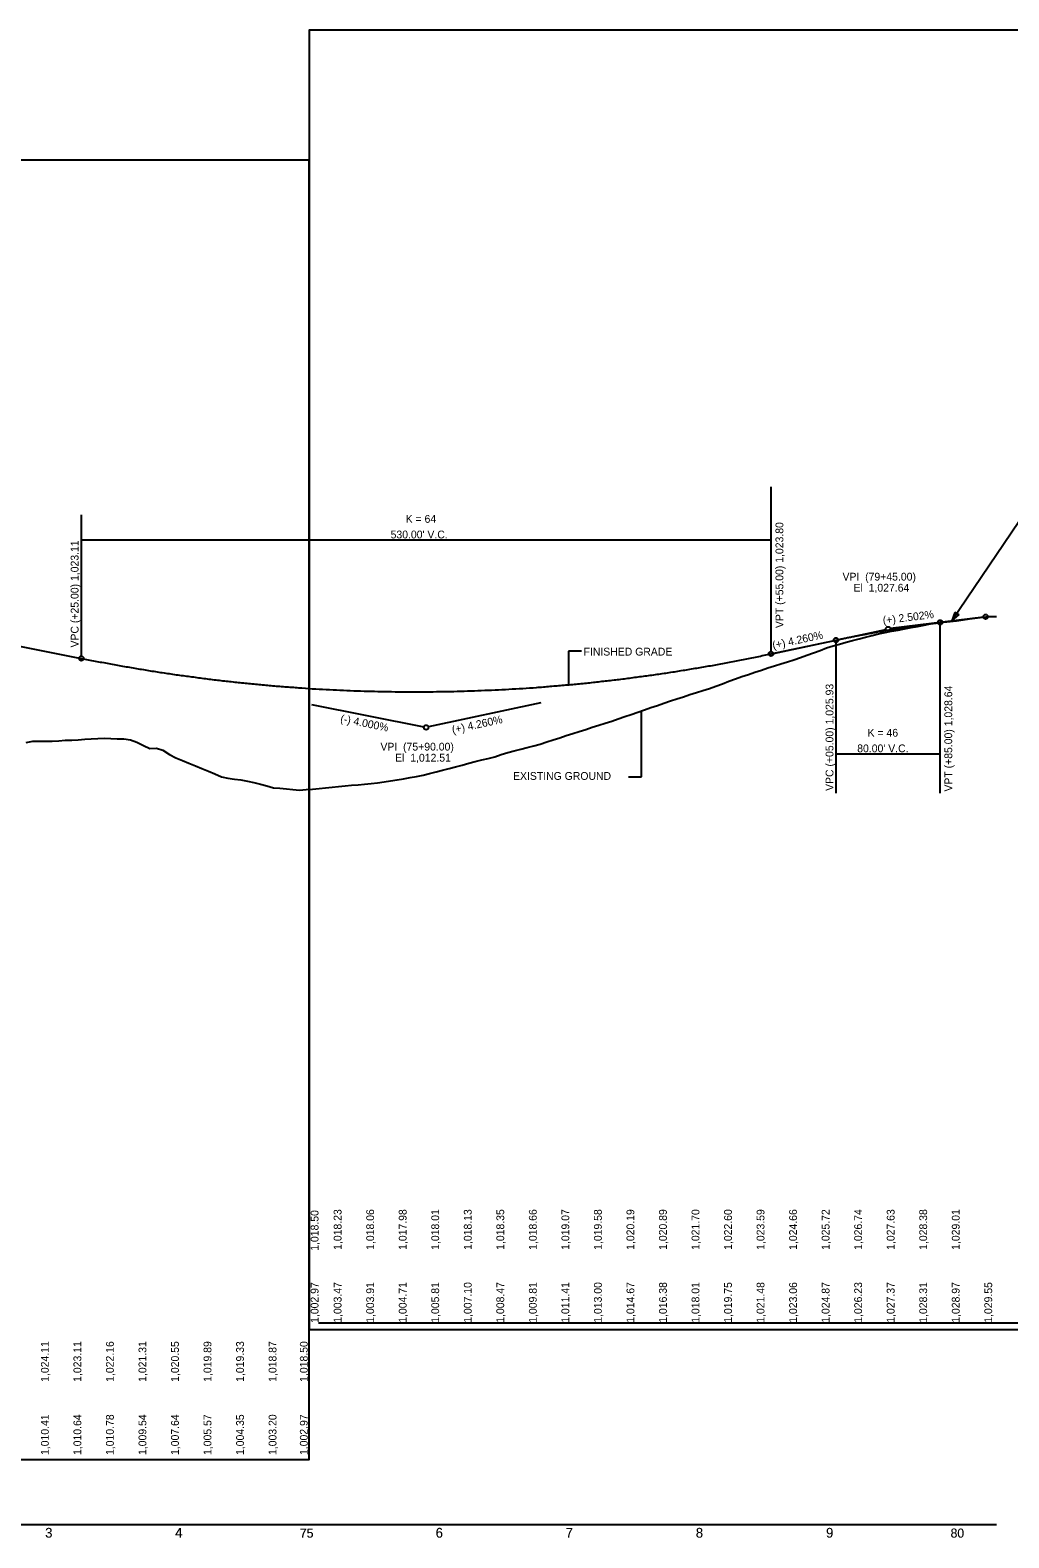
# Model space of a CAD drawing. Extents: x 889661 to 1611291, y 880491 to 1094402.
# Drawn here: x 892763 to 893515, y 880491 to 881649 of the extents above; entities that cross this region are included whole.
import ezdxf

# ---------------------------------------------------------------- set-up
doc = ezdxf.new("R2010")
doc.units = 0
for name, color, linetype in [('Default', 7, 'Continuous'), ('RD_DDB_Datum', 7, 'Continuous'), ('RD_DDB_EX_Tx', 7, 'Continuous'), ('RD_DDB_GradeTX', 7, 'Continuous'), ('RD_DDB_PI', 7, 'Continuous'), ('RD_DDB_PR_Tx', 7, 'Continuous'), ('RD_DDB_Profile_EX', 7, 'Continuous'), ('RD_DDB_Profile_PR', 7, 'Continuous'), ('RD_DDB_StaTX', 7, 'Continuous'), ('RD_DDB_StripGrade_EX', 7, 'Continuous'), ('RD_DDB_StripGrade_PR', 7, 'Continuous'), ('RD_DDB_VCLbl', 7, 'Continuous'), ('RD_GPK_Profile_Cell', 7, 'Continuous'), ('RD_TX_Profile', 7, 'Continuous')]:
    doc.layers.add(name, color=color, linetype=linetype)

msp = doc.modelspace()

# ---------------------------------------------------------------- linework, layer by layer
at = {"layer": 'Default'}
for points in [[(892976.9, 880651.1), (894476.9, 880651.1), (894476.9, 881649.3), (892976.9, 881649.3)], [(891476.9, 880551.1), (892976.9, 880551.1), (892976.9, 881549.3), (891476.9, 881549.3)]]:
    msp.add_lwpolyline(points, close=True, dxfattribs=at)
at = {"layer": 'RD_DDB_Datum'}
msp.add_line((892984.2, 880656.1), (895508.1, 880656.1), dxfattribs=at)
at = {"layer": 'RD_DDB_EX_Tx'}
for p, q in [((893232.3, 881075.7), (893232.3, 881126.2)), ((893222.5, 881075.7), (893232.3, 881075.7))]:
    msp.add_line(p, q, dxfattribs=at)
at = {"layer": 'RD_DDB_PI'}
for p, q in [((893495.2, 881198.4), (893423.7, 881189.5)), ((893333.9, 881170.5), (893420.2, 881188.9)), ((892978.7, 881131.3), (893065.2, 881114)), ((893155, 881132.4), (893068.7, 881114))]:
    msp.add_line(p, q, dxfattribs=at)
for centre in [(893496.9, 881198.6), (893421.9, 881189.2), (893066.9, 881113.6)]:
    msp.add_circle(centre, 1.75, dxfattribs=at)
at = {"layer": 'RD_DDB_PR_Tx'}
for p, q in [((893176.4, 881172.1), (893176.4, 881146.4)), ((893186.4, 881172.1), (893176.4, 881172.1))]:
    msp.add_line(p, q, dxfattribs=at)
at = {"layer": 'RD_DDB_Profile_EX'}
for points in [[(893419.6, 881186.5), (893424.6, 881187.5), (893429.6, 881188.4), (893434.6, 881189.4), (893439.6, 881190.3), (893444.6, 881191.1), (893449.6, 881192.1), (893454.6, 881193.1), (893459.6, 881193.9), (893464.6, 881194.4), (893469.6, 881194.9), (893474.6, 881195.6), (893479.6, 881196.3), (893484.6, 881197), (893489.6, 881197.7), (893494.6, 881198.4), (893499.6, 881198.8), (893504.6, 881198.8), (893505.3, 881198.8)], [(892919.6, 881073.8), (892924.6, 881073.2), (892929.6, 881072.4), (892934.6, 881071.2), (892939.6, 881070), (892944.6, 881068.6), (892949.6, 881067.3), (892954.6, 881066.8), (892959.6, 881066.3), (892964.6, 881066), (892969.6, 881065.4), (892974.6, 881065.8), (892979.6, 881066.1), (892984.6, 881066.7), (892989.6, 881067.3), (892994.6, 881067.8), (892999.6, 881068.2), (893004.6, 881068.7), (893009.6, 881069.1), (893014.6, 881069.5), (893019.6, 881070), (893024.6, 881070.4), (893029.6, 881070.9), (893034.6, 881071.7), (893039.6, 881072.5), (893044.6, 881073.4), (893049.6, 881074.2), (893054.6, 881075.1), (893059.6, 881075.9), (893064.6, 881076.9), (893069.6, 881078.2), (893074.6, 881079.5), (893079.6, 881080.8), (893084.6, 881082.1), (893089.6, 881083.4), (893094.6, 881084.7), (893099.6, 881086), (893104.6, 881087.3), (893109.6, 881088.6), (893114.6, 881089.8), (893119.6, 881091.1), (893124.6, 881092.7), (893129.6, 881094.2), (893134.6, 881095.5), (893139.6, 881096.9), (893144.6, 881098.2), (893149.6, 881099.5), (893154.6, 881100.8), (893159.6, 881102.5), (893164.6, 881104.1), (893169.6, 881105.7), (893174.6, 881107.4), (893179.6, 881109), (893184.6, 881110.5), (893189.6, 881112.1), (893194.6, 881113.7), (893199.6, 881115.3), (893204.6, 881116.9), (893209.6, 881118.5), (893214.6, 881120.2), (893219.6, 881121.9), (893224.6, 881123.6), (893229.6, 881125.3), (893234.6, 881127.1), (893239.6, 881128.8), (893244.6, 881130.5), (893249.6, 881132.2), (893254.6, 881133.9), (893259.6, 881135.5), (893264.6, 881137.2), (893269.6, 881138.8), (893274.6, 881140.4), (893279.6, 881142), (893284.6, 881143.6), (893289.6, 881145.4), (893294.6, 881147.2), (893299.6, 881149), (893304.6, 881150.8), (893309.6, 881152.6), (893314.6, 881154.3), (893319.6, 881156.1), (893324.6, 881157.7), (893329.6, 881159.3), (893334.6, 881160.9), (893339.6, 881162.5), (893344.6, 881164.1), (893349.6, 881165.6), (893354.6, 881167.2), (893359.6, 881169.1), (893364.6, 881170.9), (893369.6, 881172.8), (893374.6, 881174.7), (893379.6, 881176.3), (893384.6, 881177.6), (893389.6, 881179), (893394.6, 881180.3), (893399.6, 881181.6), (893404.6, 881182.9), (893409.6, 881184.3), (893414.6, 881185.4), (893419.6, 881186.5)], [(892759.6, 881102), (892764.6, 881103), (892769.6, 881103), (892774.6, 881103.1), (892779.6, 881103.1), (892784.6, 881103.3), (892789.6, 881103.7), (892794.6, 881103.9), (892799.6, 881104.1), (892804.6, 881104.5), (892809.6, 881104.9), (892814.6, 881105.2), (892819.6, 881105.3), (892824.6, 881105.1), (892829.6, 881104.8), (892834.6, 881104.8), (892839.6, 881104), (892844.6, 881102.2), (892849.6, 881099.8), (892854.6, 881097.5), (892859.6, 881097.6), (892864.6, 881096.2), (892869.6, 881092.8), (892874.6, 881090.2), (892879.6, 881088.1), (892884.6, 881086.1), (892889.6, 881084), (892894.6, 881081.9), (892899.6, 881079.9), (892904.6, 881077.8), (892909.6, 881075.7), (892914.6, 881074.7), (892919.6, 881073.8)]]:
    msp.add_lwpolyline(points, dxfattribs=at)
at = {"layer": 'RD_DDB_Profile_PR'}
for p, q in [((893461.9, 881194.3), (893496.9, 881198.6)), ((892666.9, 881193.6), (892801.9, 881166.6)), ((893331.9, 881170.1), (893381.9, 881180.7))]:
    msp.add_line(p, q, dxfattribs=at)
for points in [[(893381.9, 881180.7), (893383.5, 881181.1), (893385.1, 881181.4), (893386.7, 881181.7), (893388.3, 881182.1), (893389.9, 881182.4), (893391.5, 881182.7), (893393.1, 881183), (893394.7, 881183.4), (893396.3, 881183.7), (893397.9, 881184), (893399.5, 881184.3), (893401.1, 881184.6), (893402.7, 881184.9), (893404.3, 881185.2), (893405.9, 881185.5), (893407.5, 881185.8), (893409.1, 881186.1), (893410.7, 881186.4), (893412.3, 881186.7), (893413.9, 881187), (893415.5, 881187.3), (893417.1, 881187.5), (893418.7, 881187.8), (893420.3, 881188.1), (893421.9, 881188.4), (893423.5, 881188.6), (893425.1, 881188.9), (893426.7, 881189.2), (893428.3, 881189.4), (893429.9, 881189.7), (893431.5, 881189.9), (893433.1, 881190.2), (893434.7, 881190.4), (893436.3, 881190.7), (893437.9, 881190.9), (893439.5, 881191.2), (893441.1, 881191.4), (893442.7, 881191.6), (893444.3, 881191.9), (893445.9, 881192.1), (893447.5, 881192.3), (893449.1, 881192.6), (893450.7, 881192.8), (893452.3, 881193), (893453.9, 881193.2), (893455.5, 881193.4), (893457.1, 881193.6), (893458.7, 881193.8), (893460.3, 881194.1), (893461.9, 881194.3)], [(892801.9, 881166.6), (892812.5, 881164.6), (892823.1, 881162.6), (892833.7, 881160.7), (892844.3, 881158.9), (892854.9, 881157.1), (892865.5, 881155.5), (892876.1, 881153.9), (892886.7, 881152.5), (892897.3, 881151.1), (892907.9, 881149.8), (892918.5, 881148.6), (892929.1, 881147.5), (892939.7, 881146.5), (892950.3, 881145.5), (892960.9, 881144.7), (892971.5, 881143.9), (892982.1, 881143.2), (892992.7, 881142.7), (893003.3, 881142.2), (893013.9, 881141.7), (893024.5, 881141.4), (893035.1, 881141.2), (893045.7, 881141), (893056.3, 881141), (893066.9, 881141), (893077.5, 881141.1), (893088.1, 881141.3), (893098.7, 881141.6), (893109.3, 881142), (893119.9, 881142.4), (893130.5, 881143), (893141.1, 881143.6), (893151.7, 881144.3), (893162.3, 881145.2), (893172.9, 881146.1), (893183.5, 881147), (893194.1, 881148.1), (893204.7, 881149.3), (893215.3, 881150.5), (893225.9, 881151.9), (893236.5, 881153.3), (893247.1, 881154.8), (893257.7, 881156.4), (893268.3, 881158.1), (893278.9, 881159.9), (893289.5, 881161.7), (893300.1, 881163.7), (893310.7, 881165.7), (893321.3, 881167.9), (893331.9, 881170.1)]]:
    msp.add_spline(points, degree=3, dxfattribs=at)
at = {"layer": 'RD_DDB_VCLbl'}
for p, q in [((893331.9, 881298.4), (893331.9, 881171.8)), ((892801.9, 881276.9), (892801.9, 881168.4)), ((892801.9, 881257.6), (893331.9, 881257.6)), ((893461.9, 881063.2), (893461.9, 881192.5)), ((893381.9, 881063.2), (893381.9, 881179)), ((893381.9, 881093.2), (893461.9, 881093.2))]:
    msp.add_line(p, q, dxfattribs=at)
for centre in [(893461.9, 881194.3), (893381.9, 881180.7), (892801.9, 881166.6), (893331.9, 881170.1)]:
    msp.add_circle(centre, 1.75, dxfattribs=at)
at = {"layer": 'RD_GPK_Profile_Cell'}
msp.add_line((890419.6, 880501.1), (893505.3, 880501.1), dxfattribs=at)
at = {"layer": 'RD_TX_Profile'}
msp.add_lwpolyline([(893524.2, 881271.5), (893522.4, 881271.5), (893470.9, 881195.4)], dxfattribs=at)
msp.add_lwpolyline([(893473.2, 881202), (893470.9, 881195.4), (893476.2, 881200)], close=True, dxfattribs=at)

# ---------------------------------------------------------------- texts
at = {"layer": 'RD_DDB_EX_Tx'}
msp.add_text('EXISTING GROUND', height=6, dxfattribs=at).set_placement((893133.7, 881073.3))
at = {"layer": 'RD_DDB_GradeTX'}
for s, rotation, p in [('(+) 2.502%', 7.1304, (893418.2, 881192.8)), ('(+) 4.260%', 12.0243, (893333.7, 881173.7)), ('(-) 4.000%', 348.6902, (893000.6, 881117.7)), ('(+) 4.260%', 12.0243, (893087.4, 881108.8))]:
    msp.add_text(s, height=6, rotation=rotation, dxfattribs=at).set_placement(p)
at = {"layer": 'RD_DDB_PI'}
for s, p in [('VPI  (79+45.00)', (893386.9, 881226.4)), ('El  1,027.64', (893395.4, 881217.9)), ('VPI  (75+90.00)', (893031.8, 881095.8)), ('El  1,012.51', (893043.1, 881087.3))]:
    msp.add_text(s, height=6, dxfattribs=at).set_placement(p)
at = {"layer": 'RD_DDB_PR_Tx'}
msp.add_text('FINISHED GRADE', height=6, dxfattribs=at).set_placement((893187.9, 881168.8))
at = {"layer": 'RD_DDB_StaTX'}
for s, height, p in [('3', 7.5, (892774.1, 880491.1)), ('3', 7.5, (892774.2, 880491.1)), ('3', 7.5, (892774.2, 880491.1)), ('4', 7.5, (892873.9, 880491.1)), ('4', 7.5, (892874.2, 880491.1)), ('4', 7.5, (892874.2, 880491.1)), ('75', 7, (892969.8, 880491.1)), ('75', 7, (892970, 880491.1)), ('75', 7, (892970, 880491.1)), ('6', 7.5, (893074.2, 880491.1)), ('6', 7.5, (893074.2, 880491.1)), ('6', 7.5, (893074.3, 880491.1)), ('7', 7.5, (893174.1, 880491.1)), ('7', 7.5, (893174.2, 880491.1)), ('7', 7.5, (893174.2, 880491.1)), ('8', 7.5, (893274.1, 880491.1)), ('8', 7.5, (893274.2, 880491.1)), ('8', 7.5, (893274.2, 880491.1)), ('9', 7.5, (893374.2, 880491.1)), ('9', 7.5, (893374.2, 880491.1)), ('9', 7.5, (893374.3, 880491.1)), ('80', 7, (893469.9, 880491.1)), ('80', 7, (893470, 880491.1)), ('80', 7, (893470, 880491.1))]:
    msp.add_text(s, height=height, dxfattribs=at).set_placement(p)
at = {"layer": 'RD_DDB_StripGrade_EX'}
for s, p in [('1,002.97', (892984.2, 880656.1)), ('1,003.47', (893001.9, 880656.2)), ('1,003.91', (893026.9, 880656.2)), ('1,004.71', (893051.9, 880656.2)), ('1,005.81', (893076.9, 880656.2)), ('1,007.10', (893101.9, 880656.2)), ('1,008.47', (893126.9, 880656.2)), ('1,009.81', (893151.9, 880656.2)), ('1,011.41', (893176.9, 880656.2)), ('1,013.00', (893201.9, 880656.2)), ('1,014.67', (893226.9, 880656.2)), ('1,016.38', (893251.9, 880656.2)), ('1,018.01', (893276.9, 880656.2)), ('1,019.75', (893301.9, 880656.2)), ('1,021.48', (893326.9, 880656.2)), ('1,023.06', (893351.9, 880656.2)), ('1,024.87', (893376.9, 880656.2)), ('1,026.23', (893401.9, 880656.2)), ('1,027.37', (893426.9, 880656.2)), ('1,028.31', (893451.9, 880656.2)), ('1,028.97', (893476.9, 880656.2)), ('1,029.55', (893501.9, 880656.2)), ('1,010.41', (892776.9, 880554.6)), ('1,010.64', (892801.9, 880554.6)), ('1,010.78', (892826.9, 880554.6)), ('1,009.54', (892851.9, 880554.6)), ('1,007.64', (892876.9, 880554.6)), ('1,005.57', (892901.9, 880554.6)), ('1,004.35', (892926.9, 880554.6)), ('1,003.20', (892951.9, 880554.6)), ('1,002.97', (892975.9, 880554.6))]:
    msp.add_text(s, height=6, rotation=90, dxfattribs=at).set_placement(p)
at = {"layer": 'RD_DDB_StripGrade_PR'}
for s, p in [('1,018.50', (892984.2, 880711.5)), ('1,018.23', (893001.9, 880712.2)), ('1,018.06', (893026.9, 880712.2)), ('1,017.98', (893051.9, 880712.2)), ('1,018.01', (893076.9, 880712.2)), ('1,018.13', (893101.9, 880712.2)), ('1,018.35', (893126.9, 880712.2)), ('1,018.66', (893151.9, 880712.2)), ('1,019.07', (893176.9, 880712.2)), ('1,019.58', (893201.9, 880712.2)), ('1,020.19', (893226.9, 880712.2)), ('1,020.89', (893251.9, 880712.2)), ('1,021.70', (893276.9, 880712.2)), ('1,022.60', (893301.9, 880712.2)), ('1,023.59', (893326.9, 880712.2)), ('1,024.66', (893351.9, 880712.2)), ('1,025.72', (893376.9, 880712.2)), ('1,026.74', (893401.9, 880712.2)), ('1,027.63', (893426.9, 880712.2)), ('1,028.38', (893451.9, 880712.2)), ('1,029.01', (893476.9, 880712.2)), ('1,024.11', (892776.9, 880610.8)), ('1,023.11', (892801.9, 880610.8)), ('1,022.16', (892826.9, 880610.8)), ('1,021.31', (892851.9, 880610.8)), ('1,020.55', (892876.9, 880610.8)), ('1,019.89', (892901.9, 880610.8)), ('1,019.33', (892926.9, 880610.8)), ('1,018.87', (892951.9, 880610.8)), ('1,018.50', (892975.9, 880610.8))]:
    msp.add_text(s, height=6, rotation=90, dxfattribs=at).set_placement(p)
at = {"layer": 'RD_DDB_VCLbl'}
for s, p in [('K = 64', (893051.2, 881270.8)), ("530.00' V.C.", (893039.6, 881258.8)), ('K = 46', (893406.2, 881106.5)), ("80.00' V.C.", (893398.2, 881094.5))]:
    msp.add_text(s, height=6, dxfattribs=at).set_placement(p)
for s, p in [('VPT (+55.00) 1,023.80', (893341.4, 881189.9)), ('VPC (+25.00) 1,023.11', (892799.8, 881175)), ('VPC (+05.00) 1,025.93', (893379.9, 881064.8)), ('VPT (+85.00) 1,028.64', (893471.2, 881064.3))]:
    msp.add_text(s, height=6, rotation=90, dxfattribs=at).set_placement(p)

doc.saveas('drawing.dxf')
